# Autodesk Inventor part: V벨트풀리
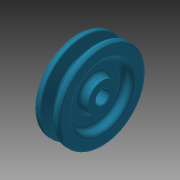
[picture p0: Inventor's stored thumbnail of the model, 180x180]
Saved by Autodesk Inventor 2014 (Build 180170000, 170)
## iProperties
Created: 2015-11
Part Number: V벨트풀리
Material: 강철, 탄소
Document SubType Name: Modeling
Designer: mduedu
Density: 7.87 g/cm^3
Mass: 380.065 g
Surface Area: 160.69 cm^2
Volume: 48.2929 cm^3
Appearance: 터키옥색
Author: mduedu
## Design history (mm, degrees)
sketch "스케치1"
  geometry: L1 (-9.5, 0)-(9.5, 0); L2 (0, 0)-(0, 35.7); L3 (-4.825, 35.7)-(-9.5, 35.7); L4 (-9.5, 35.7)-(-9.5, 0); L5 (0, 26.7)-(-2.074, 26.7); L6 (-2.074, 26.7)-(-4.825, 35.7); L7 (4.825, 35.7)-(9.5, 35.7); L8 (9.5, 35.7)-(9.5, 0); L9 (0, 26.7)-(2.074, 26.7); L10 (2.074, 26.7)-(4.825, 35.7); L11 (-9.5, 33)-(9.5, 33); 3 further points
  constraints: 22 end point, 7 point on line, 4 perpendicular, 3 symmetric about line, 1 coincident, 1 horizontal, 1 horizontal alignment, 1 midpoint, 1 vertical
  dimensions: "d0" = 19 distance of L1.start L1.end; "d2" = 71.4 diameter of L2.end L1 (derived); "d3" = 34 deg angle of L10 L6; "d4" = 6.3 distance between parallel lines of L11 L9; "d5" = 2.7 distance between parallel lines of L7 L11; "d6" = 8 distance of point (4, 33) point (-4, 33); "d7" = 66 diameter of L11 L1
revolve "회전1" sketch "스케치1" stored, may be unused: angle "d8" = 90 deg
sketch "스케치2"
  geometry: C1 r 22 at (0, 0); C2 r 11 at (0, 0); 1 further point
  constraints: 2 centre point, 2 coincident
  dimensions: "d9" = 44 diameter of C1; "d10" = 22 diameter of C2
extrude "돌출1" cut sketch "스케치2" distance "d11" = 6; taper "d12" = 0 deg
fillet "모깎기1" dims "d13" = 3
fillet "모깎기2" dims "d14" = 3
fillet "모깎기3" dims "d15" = 1, "d16" = 0.5, "d17" = 2
hole "구멍1" diameter "d20" = 10; stored, may be unused: countersink angle "d24" = 90 deg, drill point angle "d26" = 118 deg; dims "d18" = 10, "d19" = 10, "d21" = 6, "d22" = 4, "d23" = 2, "d25" = 8
sketch "스케치3"
  geometry: L1 (-1.5, 0)-(1.5, 0); L2 (1.5, 0)-(1.5, 6.4); L3 (1.5, 6.4)-(-1.5, 6.4); L4 (-1.5, 6.4)-(-1.5, 0); 2 further points
  constraints: 8 end point, 2 parallel, 1 coincident, 1 horizontal, 1 midpoint, 1 perpendicular
  dimensions: "d27" = 3 distance of L2.end L3.end; "d29" = 6.4 distance of L3.end L1.start
extrude "돌출2" cut sketch "스케치3" stored distance "d30" = 6; taper "d31" = 0 deg
chamfer "모따기1" distance "d32" = 0.5; stored, may be unused: second distance "d33" = 2, angle "d34" = 45 deg
node "솔리드1"
mirror "대칭1"
